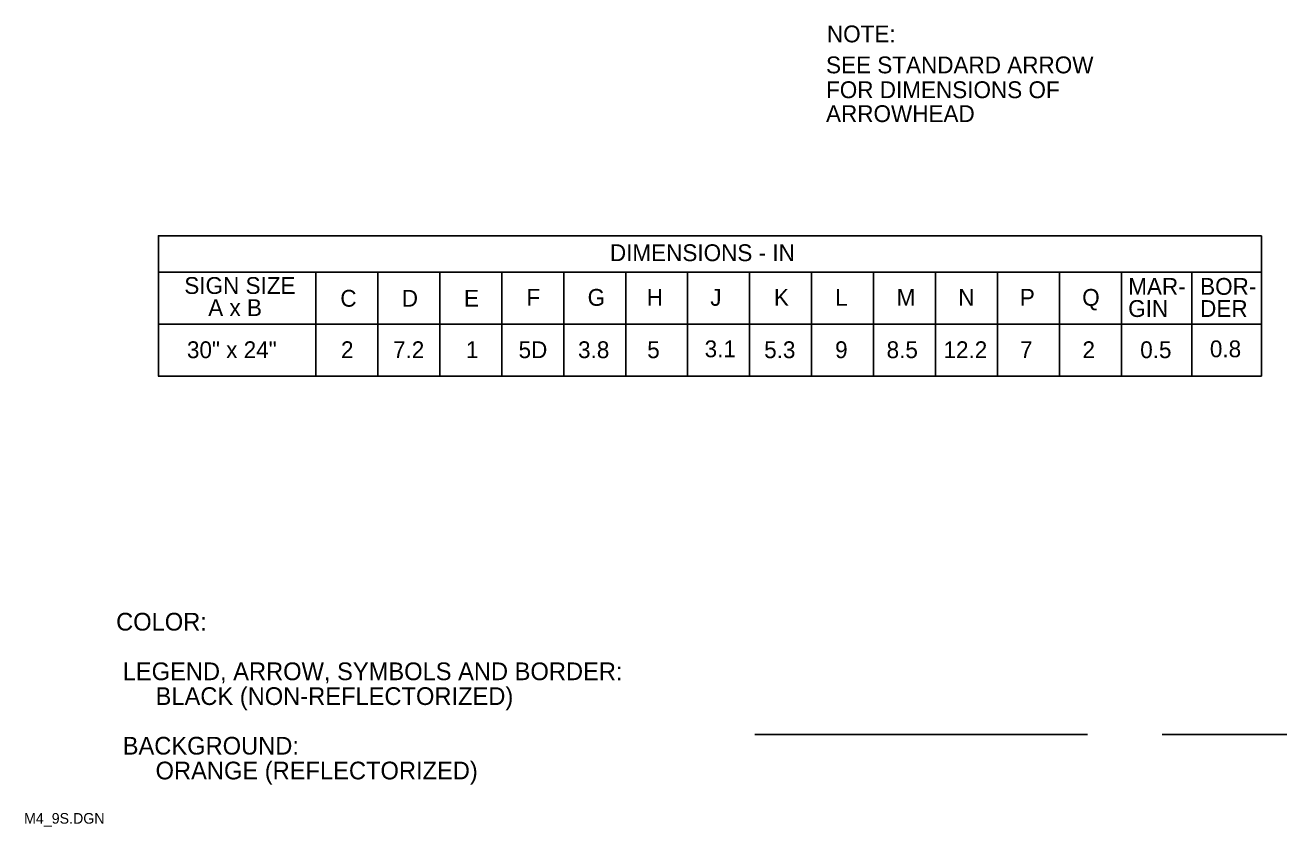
# Model space of a CAD drawing. Extents: x 0.012 to 0.191, y 0.004 to 0.259.
# Drawn here: x 0.0124 to 0.1906, y 0.0039 to 0.117 of the extents above; entities that cross this region are included whole.
import ezdxf

# ---------------------------------------------------------------- set-up
doc = ezdxf.new("R2010")
doc.units = 0
for name, color, linetype in [('1', 7, 'Continuous'), ('2', 7, 'Continuous'), ('3', 7, 'Continuous')]:
    doc.layers.add(name, color=color, linetype=linetype)

msp = doc.modelspace()

# ---------------------------------------------------------------- linework, layer by layer
at = {"layer": '1'}
for p, q in [((0.11543984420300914, 0.01694517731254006), (0.1624214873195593, 0.01694517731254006)), ((0.17295324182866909, 0.01694517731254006), (0.19056484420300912, 0.01694517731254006))]:
    msp.add_line(p, q, dxfattribs=at)
at = {"layer": '2'}
for p, q in [((0.031166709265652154, 0.0873220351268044), (0.18698482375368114, 0.0873220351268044)), ((0.0312554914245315, 0.08737500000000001), (0.0312554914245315, 0.06749703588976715)), ((0.18698482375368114, 0.0873220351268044), (0.18698482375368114, 0.06749703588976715)), ((0.18698482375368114, 0.08219703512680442), (0.03116670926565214, 0.08219703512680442)), ((0.05345829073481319, 0.08219416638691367), (0.05345829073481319, 0.06749703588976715)), ((0.06220829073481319, 0.08219416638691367), (0.06220829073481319, 0.06749703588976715)), ((0.07095829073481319, 0.08219416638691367), (0.07095829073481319, 0.06749703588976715)), ((0.0797082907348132, 0.08219416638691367), (0.0797082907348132, 0.06749703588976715)), ((0.08845829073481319, 0.08219416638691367), (0.08845829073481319, 0.06749703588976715)), ((0.09720829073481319, 0.08219416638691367), (0.09720829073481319, 0.06749703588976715)), ((0.10595829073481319, 0.08219416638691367), (0.10595829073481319, 0.06749703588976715)), ((0.1147082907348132, 0.08219416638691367), (0.1147082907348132, 0.06749703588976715)), ((0.12345829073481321, 0.08219416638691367), (0.12345829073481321, 0.06749703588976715)), ((0.13220829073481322, 0.08219416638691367), (0.13220829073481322, 0.06749703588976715)), ((0.13220829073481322, 0.08219416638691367), (0.13220829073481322, 0.06749703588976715)), ((0.1409582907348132, 0.08219416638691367), (0.1409582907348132, 0.06749703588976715)), ((0.1497082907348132, 0.08219416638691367), (0.1497082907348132, 0.06749703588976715)), ((0.1584582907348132, 0.08219416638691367), (0.1584582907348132, 0.06749703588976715)), ((0.16720829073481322, 0.08219416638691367), (0.16720829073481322, 0.06749703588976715)), ((0.17717244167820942, 0.08219416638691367), (0.17717244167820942, 0.06749703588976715)), ((0.18698482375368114, 0.07484703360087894), (0.03116670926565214, 0.07484703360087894)), ((0.18698482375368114, 0.06749703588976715), (0.03116670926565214, 0.06749703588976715))]:
    msp.add_line(p, q, dxfattribs=at)

# ---------------------------------------------------------------- texts
at = {"layer": '1'}
for s, height, p in [('NOTE:', 0.0023752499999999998, (0.12562500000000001, 0.114625)), ('SEE STANDARD ARROW', 0.0023752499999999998, (0.1255, 0.11025)), ('FOR DIMENSIONS OF', 0.0023752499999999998, (0.1255, 0.10675)), ('ARROWHEAD', 0.0023752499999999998, (0.1255, 0.10337500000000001)), ('MAR-', 0.0023752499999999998, (0.16817465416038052, 0.079)), ('BOR-', 0.0023752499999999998, (0.17832642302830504, 0.079)), ('GIN', 0.0023752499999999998, (0.16817465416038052, 0.075875)), ('DER', 0.0023752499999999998, (0.17832642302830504, 0.075875)), ('COLOR:', 0.0024997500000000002, (0.02525, 0.031624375)), (' LEGEND, ARROW, SYMBOLS AND BORDER:', 0.0024997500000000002, (0.02525, 0.024624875)), ('      BLACK (NON-REFLECTORIZED)', 0.0024997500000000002, (0.02525, 0.021125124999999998)), (' BACKGROUND:', 0.0024997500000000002, (0.02525, 0.014125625)), ('      ORANGE (REFLECTORIZED)', 0.0024997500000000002, (0.02525, 0.010625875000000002)), ('M4_9S.DGN', 0.0015, (0.01225, 0.004375))]:
    msp.add_text(s, height=height, dxfattribs=at).set_placement(p)
at = {"layer": '2'}
for s, p in [('DIMENSIONS - IN', (0.0949797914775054, 0.08375)), ('SIGN SIZE', (0.0348804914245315, 0.079125)), ('C', (0.05690869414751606, 0.07732417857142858)), ('D', (0.06559005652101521, 0.07732417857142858)), ('E', (0.07437258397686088, 0.07732417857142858)), ('F', (0.08317793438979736, 0.07744917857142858)), ('G', (0.09183208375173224, 0.07744917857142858)), ('H', (0.1001793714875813, 0.07744917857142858)), ('J', (0.10915438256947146, 0.07744917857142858)), ('K', (0.11814326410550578, 0.07744917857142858)), ('L', (0.1267940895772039, 0.07744917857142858)), ('M', (0.13547020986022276, 0.07744917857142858)), ('N', (0.1441716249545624, 0.07744917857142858)), ('P', (0.15287304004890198, 0.07744917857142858)), ('Q', (0.16167563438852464, 0.07744917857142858)), ('A x B', (0.0382554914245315, 0.076))]:
    msp.add_text(s, height=0.0023752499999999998, dxfattribs=at).set_placement(p)
at = {"layer": '3'}
for s, p in [('30" x 24"', (0.03525090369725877, 0.07006237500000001)), ('2', (0.05700694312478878, 0.07006237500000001)), ('7.2', (0.0643527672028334, 0.07006237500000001)), ('1', (0.07464153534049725, 0.07006237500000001)), ('5D', (0.08208459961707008, 0.07006237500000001)), ('3.8', (0.09048215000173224, 0.07006237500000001)), ('5', (0.10024882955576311, 0.07006237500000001)), ('3.1', (0.10835567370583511, 0.07018737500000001)), ('5.3', (0.11676037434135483, 0.07006237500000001)), ('9', (0.12678380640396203, 0.07006237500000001)), ('8.5', (0.13405565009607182, 0.07006237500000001)), ('12.2', (0.14208587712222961, 0.07006237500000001)), ('7', (0.15289478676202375, 0.07006237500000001)), ('2', (0.16171321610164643, 0.07006237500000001)), ('0.5', (0.1698704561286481, 0.07006237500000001)), ('0.8', (0.1797087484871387, 0.07018737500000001))]:
    msp.add_text(s, height=0.0023752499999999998, dxfattribs=at).set_placement(p)

doc.saveas('drawing.dxf')
